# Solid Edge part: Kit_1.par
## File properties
Sűrűség: 0,000 kg/m^3
Pontosság: 0,990
Author: ahadarics
Last saved by: ahadarics
Revision: 80
Username: ahadarics
Dokumentum tartalom típus: 0
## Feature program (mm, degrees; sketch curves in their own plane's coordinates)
base feature "unnamed BaseFeature 1"
sketch for "Furat_2" plane through (0, -49, 12) normal (0, 0, 1) x-axis (0, 1, 0)
hole "Furat_2" diameter 9.728 finite  ThreadDepth = 7.5 mm
thread "unnamed Thread 1"
chamfer "Letörés_2" setback 1.5
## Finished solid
Body 1: solid body, 91 faces, 122 edges, 38 vertices, 2 internal voids.
  Faces by surface: cylinder 28, plane 28, cone 25, torus 9, spun 1
  Edges by curve: circle 82, line 22, intersection 14, spline 4
Bounding box of the edges (mm; curved faces can reach further): 26.800 x 37.500 x 25.400, from (-13.4, -76.75, -13.4) to (13.4, -39.25, 12).
Cylindrical faces by radius (mm): R0.875 x1, R0.9 x1, R1.7 x1, R1.75 x1, R3 x2, R4 x1, R4.25 x2, R4.28 x3, R4.283 x1, R4.55 x1, R4.75 x1, R5 x3, R6 x2, R6.05 x1, R7.05 x1, R7.1 x1, R9.85 x1, R11 x2, R11.1 x1, R13.4 x1
Conical faces (half-angle, radius in mm at the cone's reference point): 0.1788 deg R5.7706 x1, 15 deg R7.05 x1, 19.7315 deg R4.0176 x1, 20 deg R5.909 x2, 20.542 deg R4.55 x1, 21.5244 deg R5.2703 x1, 24.3997 deg R4.55 x1, 30 deg R1.8366 x1, 30 deg R4.25 x1, 45 deg R1.55 x2, 45 deg R3.1 x1, 45 deg R4.25 x2, 45 deg R4.28 x1, 45 deg R6.15 x1, 45 deg R6.2 x1, 45 deg R11 x1, 45 deg R46.7132 x1, 59 deg R1 x3, 59 deg R2.1415 x1, 60 deg R10.425 x1
Toroidal faces (ring radius, tube radius in mm): R1.75 r3 x1, R3.6345 r0.2 x1, R4.2 r0.2 x1, R4.3 r0.3 x1, R5.6424 r0.4 x1, R5.85 r0.2 x1, R6.85 r0.2 x1, R6.9 r0.2 x2
Planar faces by outward normal: +x 1, +y 7, +z 6, -x 1, -y 12, -z 1
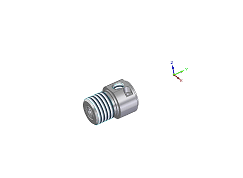
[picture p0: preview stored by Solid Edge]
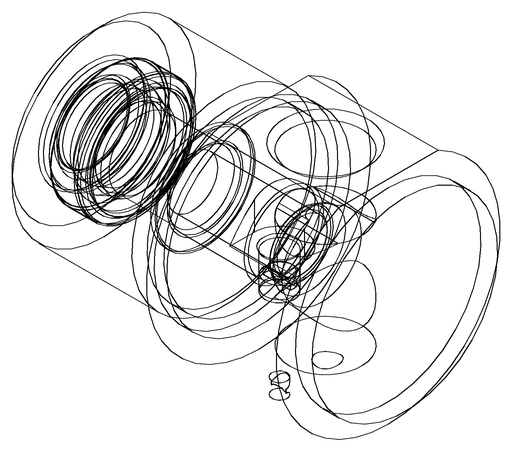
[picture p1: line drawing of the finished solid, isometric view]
